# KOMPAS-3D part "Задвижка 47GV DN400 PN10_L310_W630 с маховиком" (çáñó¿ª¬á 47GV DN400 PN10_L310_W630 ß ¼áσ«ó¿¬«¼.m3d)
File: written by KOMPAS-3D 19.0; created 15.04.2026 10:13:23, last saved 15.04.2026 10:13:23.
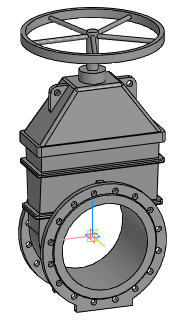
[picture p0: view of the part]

Document properties: Автор: Евгений; Полное имя файла: Z:\3.Личные\kachalov\3d для проектировщиков\2.1 Тип 47GV, 47GV.Z\Задвижка 47GV_DN40-DN600\stp_Задвижка 47GV\Задвижка 47GV DN400 PN10_L310_W630 с маховиком.m3d

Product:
- Part/product: Задвижка 47GV DN400 PN10_L310_W630 с маховиком

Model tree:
1. Операция без истории:1  (labels: Задвижка 47GV DN400 PN10_L310_W630 с маховиком)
